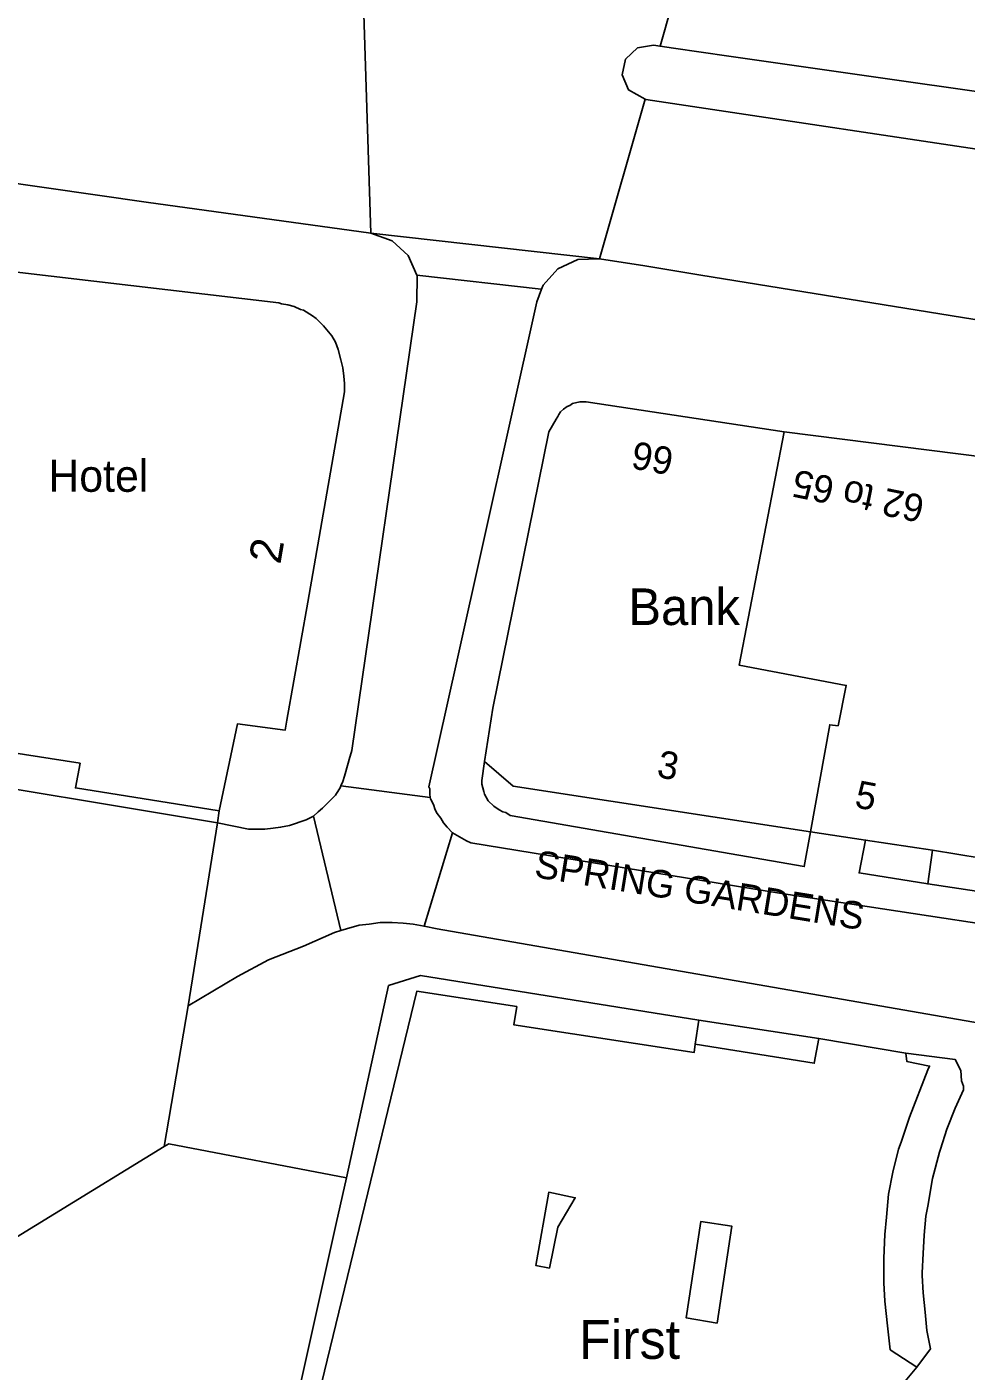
# Model space of a CAD drawing. Extents: x 529240 to 530363, y 179600 to 180767.
# Drawn here: x 529918.6 to 529969.9, y 180321.7 to 180395.2 of the extents above; entities that cross this region are included whole.
import ezdxf

# ---------------------------------------------------------------- set-up
doc = ezdxf.new("R2010")
doc.units = 0
for name, color, linetype in [('Building', 7, 'Continuous'), ('General surface', 7, 'Continuous'), ('Road Or Track', 7, 'Continuous'), ('Roadside', 7, 'Continuous'), ('Unclassified', 7, 'Continuous')]:
    doc.layers.add(name, color=color, linetype=linetype)

msp = doc.modelspace()

# ---------------------------------------------------------------- linework, layer by layer
at = {"layer": 'Building'}
for points in [[(529917.7, 180355.55), (529921.55, 180354.95), (529921.3, 180353.6), (529929.15, 180352.35), (529930.15, 180357.1), (529932.75, 180356.75), (529932.85, 180357.3), (529934, 180363.75), (529936, 180375.25), (529936, 180375.7), (529935.95, 180376.1), (529935.9, 180376.55), (529935.8, 180377), (529935.65, 180377.55), (529935.5, 180377.95), (529935.3, 180378.3), (529934.85, 180378.85), (529934.45, 180379.25), (529934.25, 180379.4), (529933.75, 180379.7), (529933.6, 180379.75), (529933.25, 180379.9), (529932.9, 180380), (529932.55, 180380.05), (529932.4, 180380.1), (529909.85, 180382.75)], [(529929.15, 180352.35), (529930.15, 180357.1), (529932.75, 180356.75), (529932.85, 180357.3), (529934, 180363.75), (529936, 180375.25), (529936, 180375.7), (529935.95, 180376.1), (529935.9, 180376.55), (529935.8, 180377), (529935.65, 180377.55), (529935.5, 180377.95), (529935.3, 180378.3), (529934.85, 180378.85), (529934.45, 180379.25), (529934.25, 180379.4), (529933.75, 180379.7), (529933.6, 180379.75), (529933.25, 180379.9), (529932.9, 180380), (529932.55, 180380.05), (529932.4, 180380.1), (529909.85, 180382.75)], [(529960, 180373.05), (529949.2, 180374.7), (529948.85, 180374.7), (529948.45, 180374.6), (529948.3, 180374.5), (529948.15, 180374.45), (529947.95, 180374.3), (529947.8, 180374.15), (529947.7, 180374), (529947.65, 180373.9), (529947.55, 180373.75), (529947.15, 180373.05), (529944.1, 180357.95), (529943.65, 180355.05)], [(529960, 180373.05), (529957.55, 180360.3), (529963.4, 180359.2), (529962.95, 180357), (529962.5, 180357.05), (529961.45, 180351.2)], [(529975.85, 180371.05), (529960, 180373.05)], [(529929.15, 180352.35), (529921.3, 180353.6), (529921.55, 180354.95), (529917.7, 180355.55), (529917.55, 180354.4), (529912.3, 180355.15)], [(529943.65, 180355.05), (529945.2, 180353.7), (529961.45, 180351.2)], [(529929.05, 180351.7), (529929.15, 180352.35)], [(529927.45, 180341.7), (529929.05, 180351.7)], [(529961.45, 180351.2), (529964.45, 180350.75)], [(529964.45, 180350.75), (529968.1, 180350.2)], [(529968.1, 180350.2), (529972.1, 180349.55)], [(529966.25, 180320.75), (529967.25, 180321.95), (529965.8, 180322.9), (529965.65, 180324.2), (529965.5, 180325.55), (529965.45, 180326.55), (529965.45, 180327.9), (529965.5, 180329.2), (529965.6, 180330.15), (529965.7, 180331.4), (529965.95, 180332.6), (529966.25, 180333.85), (529966.4, 180334.25), (529966.85, 180335.6), (529967.85, 180338.2), (529967.95, 180338.4), (529966.7, 180338.65), (529966.65, 180339.1), (529961.9, 180339.9), (529961.65, 180338.55), (529955.15, 180339.6), (529955.1, 180339.15), (529945.25, 180340.65), (529945.4, 180341.65), (529939.95, 180342.5), (529933.8, 180317.15)], [(529955.15, 180339.6), (529955.1, 180339.15), (529945.25, 180340.65), (529945.4, 180341.65), (529939.95, 180342.5), (529933.8, 180317.15)], [(529926.15, 180334), (529927.45, 180341.7)], [(529961.9, 180339.9), (529961.65, 180338.55), (529955.15, 180339.6)], [(529966.65, 180339.1), (529961.9, 180339.9)], [(529967.25, 180321.95), (529965.8, 180322.9), (529965.65, 180324.2), (529965.5, 180325.55), (529965.45, 180326.55), (529965.45, 180327.9), (529965.5, 180329.2), (529965.6, 180330.15), (529965.7, 180331.4), (529965.95, 180332.6), (529966.25, 180333.85), (529966.4, 180334.25), (529966.85, 180335.6), (529967.85, 180338.2), (529967.95, 180338.4), (529966.7, 180338.65), (529966.65, 180339.1)], [(529914.15, 180326.65), (529926.15, 180334)], [(529926.15, 180334), (529926.4, 180334.15)], [(529947.2, 180327.35), (529947.65, 180329.6), (529948.6, 180331.2), (529947.15, 180331.5), (529946.45, 180327.5), (529947.2, 180327.35)], [(529956.35, 180324.35), (529954.65, 180324.65), (529955.45, 180329.9), (529957.15, 180329.65), (529956.35, 180324.35)], [(529966.25, 180320.75), (529967.25, 180321.95)]]:
    msp.add_lwpolyline(points, dxfattribs=at)
for points in [[(529961.45, 180351.2), (529962.5, 180357.05), (529962.95, 180357), (529963.4, 180359.2), (529957.55, 180360.3), (529960, 180373.05), (529949.2, 180374.7), (529948.85, 180374.7), (529948.45, 180374.6), (529948.3, 180374.5), (529948.15, 180374.45), (529947.95, 180374.3), (529947.8, 180374.15), (529947.7, 180374), (529947.65, 180373.9), (529947.55, 180373.75), (529947.15, 180373.05), (529944.1, 180357.95), (529943.65, 180355.05), (529945.2, 180353.7)], [(529968.1, 180350.2), (529972.1, 180349.55), (529973.45, 180355.3), (529973.95, 180355.2), (529974.65, 180358.1), (529972.65, 180357.5), (529971.65, 180357.7), (529972.75, 180362), (529973.7, 180365.65), (529974.4, 180365.5), (529975.85, 180371.05), (529960, 180373.05), (529957.55, 180360.3), (529963.4, 180359.2), (529962.95, 180357), (529962.5, 180357.05), (529961.45, 180351.2), (529964.45, 180350.75)], [(529912.3, 180355.15), (529912.2, 180354.5), (529911.5, 180349.9), (529911.05, 180347), (529908.45, 180345.5), (529904.9, 180343.5), (529904.15, 180343.05), (529914.15, 180326.65), (529926.15, 180334), (529927.45, 180341.7), (529929.05, 180351.7), (529929.15, 180352.35), (529921.3, 180353.6), (529921.55, 180354.95), (529917.7, 180355.55), (529917.55, 180354.4)], [(529947.2, 180327.35), (529947.65, 180329.6), (529948.6, 180331.2), (529947.15, 180331.5), (529946.45, 180327.5)], [(529956.35, 180324.35), (529957.15, 180329.65), (529955.45, 180329.9), (529954.65, 180324.65)]]:
    msp.add_lwpolyline(points, close=True, dxfattribs=at)
at = {"layer": 'General surface'}
for points in [[(529943.65, 180355.05), (529943.5, 180354), (529943.5, 180353.8), (529943.6, 180353.4), (529943.65, 180353.25), (529943.85, 180352.9), (529944.15, 180352.6), (529944.45, 180352.4), (529944.65, 180352.3), (529944.8, 180352.25), (529945.05, 180352.1), (529961.1, 180349.3), (529961.45, 180351.2), (529945.2, 180353.7)], [(529967.85, 180348.35), (529968.1, 180350.2), (529964.45, 180350.75), (529964.1, 180348.95)], [(529971.85, 180347.75), (529972.1, 180349.55), (529968.1, 180350.2), (529967.85, 180348.35)], [(529961.9, 180339.9), (529955.35, 180340.9), (529955.15, 180339.6), (529961.65, 180338.55)], [(529967.25, 180321.95), (529968, 180322.95), (529967.8, 180323.95), (529967.7, 180324.95), (529967.6, 180326), (529967.55, 180326.95), (529967.55, 180327.1), (529967.6, 180328.15), (529967.65, 180329.15), (529967.75, 180330.2), (529967.85, 180330.75), (529968.1, 180332.25), (529968.5, 180333.7), (529968.55, 180333.85), (529968.9, 180334.95), (529969.35, 180336.1), (529969.8, 180337.1), (529969.8, 180337.3), (529969.7, 180337.6), (529969.65, 180338.15), (529969.35, 180338.75), (529966.65, 180339.1), (529966.7, 180338.65), (529967.95, 180338.4), (529967.85, 180338.2), (529966.85, 180335.6), (529966.4, 180334.25), (529966.25, 180333.85), (529965.95, 180332.6), (529965.7, 180331.4), (529965.6, 180330.15), (529965.5, 180329.2), (529965.45, 180327.9), (529965.45, 180326.55), (529965.5, 180325.55), (529965.65, 180324.2), (529965.8, 180322.9)], [(529947.2, 180327.35), (529947.65, 180329.6), (529948.6, 180331.2), (529947.15, 180331.5), (529946.45, 180327.5)], [(529956.35, 180324.35), (529957.15, 180329.65), (529955.45, 180329.9), (529954.65, 180324.65)]]:
    msp.add_lwpolyline(points, close=True, dxfattribs=at)
for points in [[(529933.8, 180317.15), (529939.95, 180342.5), (529945.4, 180341.65), (529945.25, 180340.65), (529955.1, 180339.15), (529955.15, 180339.6), (529955.35, 180340.9), (529940.15, 180343.35), (529938.4, 180342.8), (529936.1, 180332.3), (529935.54, 180329.79), (529932.3, 180315.2)], [(529932.3, 180315.2), (529935.54, 180329.79), (529936.1, 180332.3), (529926.4, 180334.15), (529926.15, 180334), (529914.15, 180326.65)]]:
    msp.add_lwpolyline(points, dxfattribs=at)
at = {"layer": 'Road Or Track'}
for points in [[(529936.88, 180401.04), (529915.75, 180404.08), (529868.32, 180410.91), (529862.53, 180412.05), (529857.93, 180413.41), (529853.46, 180415.16), (529852.45, 180415.73), (529846.38, 180413.91), (529846.36, 180413.54), (529845.88, 180413.25), (529847.53, 180409.14), (529847.95, 180408.85), (529848.85, 180406.97), (529848.84, 180406.5), (529848.33, 180406.26), (529847.75, 180400.26), (529865.5, 180397.61), (529865.59, 180397.6), (529878.05, 180392.38), (529925.17, 180385.6), (529937.44, 180383.91)], [(529937.44, 180383.91), (529949.92, 180382.52), (529952.41, 180391.23), (529951.5, 180391.74), (529951.16, 180392.56), (529951.35, 180393.43), (529952, 180394.04), (529952.87, 180394.18), (529953.23, 180394.13), (529954.48, 180398.5), (529936.88, 180401.04)], [(530005.28, 180368.4), (530006.1, 180378.46), (530001.57, 180380.79), (530000, 180381.45), (529996.86, 180382.76), (529992.02, 180384.36), (529987.07, 180385.57), (529972.72, 180388.17), (529953.54, 180391.05), (529952.45, 180391.21), (529952.41, 180391.23), (529949.92, 180382.52), (529952.4, 180382.12), (529955.46, 180381.62), (529986.51, 180376.59), (529989.29, 180377.65), (529989.92, 180377.68), (529991.21, 180377.23), (529996.68, 180375.3), (529996.77, 180375.26), (529998.99, 180374.16), (530000, 180373.48), (530001.47, 180372.48), (530003.69, 180370.47)], [(529949.92, 180382.52), (529937.44, 180383.91), (529938.6, 180383.5), (529939.47, 180382.69), (529939.95, 180381.62), (529946.73, 180380.86), (529946.76, 180380.85), (529946.85, 180381.08), (529947.65, 180381.97), (529948.73, 180382.48)], [(529935.8, 180353.71), (529940.68, 180353.08), (529940.65, 180353.25), (529940.65, 180353.55), (529940.6, 180353.65), (529942.15, 180360.6), (529946.5, 180380.16), (529946.76, 180380.85), (529946.73, 180380.86), (529939.95, 180381.62), (529939.96, 180381.6), (529939.95, 180380.17), (529936.4, 180355.65), (529936.25, 180355.15), (529936.2, 180354.95), (529936, 180354.25), (529935.9, 180353.95)], [(529934.3, 180352.05), (529935.8, 180345.81), (529936.1, 180345.9), (529936.8, 180346.1), (529937.35, 180346.15), (529937.95, 180346.25), (529938.6, 180346.25), (529939.2, 180346.2), (529939.75, 180346.15), (529940.34, 180346.04), (529941.9, 180351.15), (529941.6, 180351.45), (529941.4, 180351.7), (529941.25, 180351.95), (529941.05, 180352.2), (529940.95, 180352.4), (529940.85, 180352.7), (529940.7, 180353), (529940.68, 180353.08), (529935.8, 180353.71), (529935.75, 180353.6), (529935.55, 180353.3), (529935.5, 180353.2), (529934.8, 180352.5), (529934.55, 180352.3)], [(529927.45, 180341.7), (529930.15, 180343.3), (529931.85, 180344.2), (529933.75, 180344.95), (529935.45, 180345.7), (529935.8, 180345.81), (529934.3, 180352.05), (529933.9, 180351.85), (529933, 180351.55), (529932.5, 180351.45), (529932.1, 180351.4), (529931.65, 180351.35), (529930.75, 180351.35), (529929.05, 180351.7)], [(529940.34, 180346.04), (529941.05, 180345.9), (529973.18, 180340.31), (529974.53, 180340.07), (529982.61, 180338.66), (529982.88, 180338.55), (529982.9, 180338.56), (529984.57, 180339.7), (529986.98, 180340.9), (529989.55, 180341.72), (529985.6, 180343.91), (529959.75, 180347.85), (529942.9, 180350.6), (529942.65, 180350.7), (529941.9, 180351.15)]]:
    msp.add_lwpolyline(points, close=True, dxfattribs=at)
for points in [[(529954.48, 180398.5), (529953.23, 180394.13), (529953.97, 180394.02), (529956.99, 180393.59), (529979.3, 180390.4), (529985.56, 180389.7), (529994.89, 180389.4), (529999.38, 180389.68), (530000, 180389.77), (530000.2, 180389.8), (530003.82, 180390.38), (530011.94, 180392.6), (530010.83, 180400.08)], [(529953.23, 180394.13), (529952.87, 180394.18), (529952, 180394.04), (529951.35, 180393.43), (529951.16, 180392.56), (529951.5, 180391.74), (529952.41, 180391.23)], [(530011.94, 180392.6), (530003.82, 180390.38), (530000.2, 180389.8), (530000, 180389.77), (529999.38, 180389.68), (529994.89, 180389.4), (529985.56, 180389.7), (529979.3, 180390.4), (529956.99, 180393.59), (529953.97, 180394.02), (529953.23, 180394.13)], [(529937.44, 180383.91), (529925.17, 180385.6), (529878.05, 180392.38)], [(529952.41, 180391.23), (529952.45, 180391.21), (529953.54, 180391.05), (529972.72, 180388.17), (529987.07, 180385.57), (529992.02, 180384.36), (529996.86, 180382.76), (530000, 180381.45), (530001.57, 180380.79), (530006.1, 180378.46)], [(529939.95, 180381.62), (529939.47, 180382.69), (529938.6, 180383.5), (529937.44, 180383.91)], [(529949.92, 180382.52), (529937.44, 180383.91)], [(529946.76, 180380.85), (529946.85, 180381.08), (529947.65, 180381.97), (529948.73, 180382.48), (529949.92, 180382.52)], [(529949.92, 180382.52), (529952.4, 180382.12), (529955.46, 180381.62), (529986.51, 180376.59), (529989.29, 180377.65), (529989.92, 180377.68), (529991.21, 180377.23), (529996.68, 180375.3), (529996.77, 180375.26), (529998.99, 180374.16), (530000, 180373.48), (530001.47, 180372.48), (530003.69, 180370.47), (530005.28, 180368.4)], [(529939.95, 180380.17), (529939.96, 180381.6), (529939.95, 180381.62)], [(529946.76, 180380.85), (529946.73, 180380.86), (529939.95, 180381.62)], [(529940.68, 180353.08), (529940.65, 180353.25), (529940.65, 180353.55), (529940.6, 180353.65), (529942.15, 180360.6), (529946.5, 180380.16), (529946.76, 180380.85)], [(529939.95, 180380.17), (529936.4, 180355.65)], [(529935.8, 180353.71), (529935.9, 180353.95), (529936, 180354.25), (529936.2, 180354.95), (529936.25, 180355.15), (529936.4, 180355.65)], [(529934.3, 180352.05), (529934.55, 180352.3), (529934.8, 180352.5), (529935.5, 180353.2), (529935.55, 180353.3), (529935.75, 180353.6), (529935.8, 180353.71)], [(529941.9, 180351.15), (529941.6, 180351.45), (529941.4, 180351.7), (529941.25, 180351.95), (529941.05, 180352.2), (529940.95, 180352.4), (529940.85, 180352.7), (529940.7, 180353), (529940.68, 180353.08)], [(529929.05, 180351.7), (529930.75, 180351.35), (529931.65, 180351.35), (529932.1, 180351.4), (529932.5, 180351.45), (529933, 180351.55), (529933.9, 180351.85), (529934.3, 180352.05)], [(529989.55, 180341.72), (529985.6, 180343.91), (529959.75, 180347.85), (529942.9, 180350.6), (529942.65, 180350.7), (529941.9, 180351.15)], [(529940.34, 180346.04), (529939.75, 180346.15), (529939.2, 180346.2), (529938.6, 180346.25), (529937.95, 180346.25), (529937.35, 180346.15), (529936.8, 180346.1), (529936.1, 180345.9), (529935.8, 180345.81)], [(529935.8, 180345.81), (529935.45, 180345.7), (529933.75, 180344.95), (529931.85, 180344.2), (529930.15, 180343.3), (529927.45, 180341.7)], [(529973.18, 180340.31), (529941.05, 180345.9), (529940.34, 180346.04)]]:
    msp.add_lwpolyline(points, dxfattribs=at)
at = {"layer": 'Roadside'}
for points in [[(529979.3, 180390.4), (529956.99, 180393.59), (529953.97, 180394.02), (529953.23, 180394.13), (529952.87, 180394.18), (529952, 180394.04), (529951.35, 180393.43), (529951.16, 180392.56), (529951.5, 180391.74), (529952.41, 180391.23), (529952.45, 180391.21), (529953.54, 180391.05), (529972.72, 180388.17)], [(529909.85, 180382.75), (529932.4, 180380.1), (529932.55, 180380.05), (529932.9, 180380), (529933.25, 180379.9), (529933.6, 180379.75), (529933.75, 180379.7), (529934.25, 180379.4), (529934.45, 180379.25), (529934.85, 180378.85), (529935.3, 180378.3), (529935.5, 180377.95), (529935.65, 180377.55), (529935.8, 180377), (529935.9, 180376.55), (529935.95, 180376.1), (529936, 180375.7), (529936, 180375.25), (529934, 180363.75), (529932.85, 180357.3), (529932.75, 180356.75), (529930.15, 180357.1), (529929.15, 180352.35), (529929.05, 180351.7), (529930.75, 180351.35), (529931.65, 180351.35), (529932.1, 180351.4), (529932.5, 180351.45), (529933, 180351.55), (529933.9, 180351.85), (529934.3, 180352.05), (529934.55, 180352.3), (529934.8, 180352.5), (529935.5, 180353.2), (529935.55, 180353.3), (529935.75, 180353.6), (529935.8, 180353.71), (529935.9, 180353.95), (529936, 180354.25), (529936.2, 180354.95), (529936.25, 180355.15), (529936.4, 180355.65), (529939.95, 180380.17), (529939.96, 180381.6), (529939.95, 180381.62), (529939.47, 180382.69), (529938.6, 180383.5), (529937.44, 180383.91), (529925.17, 180385.6), (529878.05, 180392.38)], [(529986.51, 180376.59), (529955.46, 180381.62), (529952.4, 180382.12), (529949.92, 180382.52), (529948.73, 180382.48), (529947.65, 180381.97), (529946.85, 180381.08), (529946.76, 180380.85), (529946.5, 180380.16), (529942.15, 180360.6), (529940.6, 180353.65), (529940.65, 180353.55), (529940.65, 180353.25), (529940.68, 180353.08), (529940.7, 180353), (529940.85, 180352.7), (529940.95, 180352.4), (529941.05, 180352.2), (529941.25, 180351.95), (529941.4, 180351.7), (529941.6, 180351.45), (529941.9, 180351.15), (529942.65, 180350.7), (529942.9, 180350.6), (529959.75, 180347.85), (529985.6, 180343.91)], [(529975.85, 180371.05), (529960, 180373.05), (529949.2, 180374.7), (529948.85, 180374.7), (529948.45, 180374.6), (529948.3, 180374.5), (529948.15, 180374.45), (529947.95, 180374.3), (529947.8, 180374.15), (529947.7, 180374), (529947.65, 180373.9), (529947.55, 180373.75), (529947.15, 180373.05), (529944.1, 180357.95), (529943.65, 180355.05), (529943.5, 180354), (529943.5, 180353.8), (529943.6, 180353.4), (529943.65, 180353.25), (529943.85, 180352.9), (529944.15, 180352.6), (529944.45, 180352.4), (529944.65, 180352.3), (529944.8, 180352.25), (529945.05, 180352.1), (529961.1, 180349.3), (529961.45, 180351.2), (529964.45, 180350.75), (529964.1, 180348.95), (529967.85, 180348.35), (529971.85, 180347.75)], [(529973.18, 180340.31), (529941.05, 180345.9), (529940.34, 180346.04), (529939.75, 180346.15), (529939.2, 180346.2), (529938.6, 180346.25), (529937.95, 180346.25), (529937.35, 180346.15), (529936.8, 180346.1), (529936.1, 180345.9), (529935.8, 180345.81), (529935.45, 180345.7), (529933.75, 180344.95), (529931.85, 180344.2), (529930.15, 180343.3), (529927.45, 180341.7), (529926.15, 180334), (529926.4, 180334.15), (529936.1, 180332.3), (529938.4, 180342.8), (529940.15, 180343.35), (529955.35, 180340.9), (529961.9, 180339.9), (529966.65, 180339.1), (529969.35, 180338.75), (529969.65, 180338.15), (529969.7, 180337.6), (529969.8, 180337.3), (529969.8, 180337.1), (529969.35, 180336.1), (529968.9, 180334.95), (529968.55, 180333.85), (529968.5, 180333.7), (529968.1, 180332.25), (529967.85, 180330.75), (529967.75, 180330.2), (529967.65, 180329.15), (529967.6, 180328.15), (529967.55, 180327.1), (529967.55, 180326.95), (529967.6, 180326), (529967.7, 180324.95), (529967.8, 180323.95), (529968, 180322.95), (529967.25, 180321.95), (529966.25, 180320.75)]]:
    msp.add_lwpolyline(points, dxfattribs=at)
at = {"layer": 'Unclassified'}
for points in [[(529937.44, 180383.91), (529936.88, 180401.04)], [(529954.48, 180398.5), (529953.23, 180394.13)], [(529952.41, 180391.23), (529949.92, 180382.52)], [(529943.65, 180355.05), (529943.5, 180354), (529943.5, 180353.8), (529943.6, 180353.4), (529943.65, 180353.25), (529943.85, 180352.9), (529944.15, 180352.6), (529944.45, 180352.4), (529944.65, 180352.3), (529944.8, 180352.25), (529945.05, 180352.1), (529961.1, 180349.3), (529961.45, 180351.2)], [(529912.2, 180354.5), (529929.05, 180351.7)], [(529940.68, 180353.08), (529935.8, 180353.71)], [(529934.3, 180352.05), (529935.8, 180345.81)], [(529941.9, 180351.15), (529940.34, 180346.04)], [(529964.45, 180350.75), (529964.1, 180348.95), (529967.85, 180348.35)], [(529967.85, 180348.35), (529968.1, 180350.2)], [(529967.85, 180348.35), (529971.85, 180347.75)], [(529940.15, 180343.35), (529938.4, 180342.8), (529936.1, 180332.3)], [(529955.35, 180340.9), (529940.15, 180343.35)], [(529955.35, 180340.9), (529955.15, 180339.6)], [(529961.9, 180339.9), (529955.35, 180340.9)], [(529967.25, 180321.95), (529968, 180322.95), (529967.8, 180323.95), (529967.7, 180324.95), (529967.6, 180326), (529967.55, 180326.95), (529967.55, 180327.1), (529967.6, 180328.15), (529967.65, 180329.15), (529967.75, 180330.2), (529967.85, 180330.75), (529968.1, 180332.25), (529968.5, 180333.7), (529968.55, 180333.85), (529968.9, 180334.95), (529969.35, 180336.1), (529969.8, 180337.1), (529969.8, 180337.3), (529969.7, 180337.6), (529969.65, 180338.15), (529969.35, 180338.75), (529966.65, 180339.1)], [(529926.4, 180334.15), (529936.1, 180332.3)], [(529936.1, 180332.3), (529935.54, 180329.79), (529932.3, 180315.2), (529935.8, 180310.2)]]:
    msp.add_lwpolyline(points, dxfattribs=at)

# ---------------------------------------------------------------- texts
at = {"layer": 'Road Or Track'}
msp.add_text('SPRING GARDENS', height=1.5, rotation=350.8, dxfattribs=at).set_placement((529946.31, 180348.73))
at = {"layer": 'Unclassified'}
for s, height, rotation, p in [('66', 1.5, 169.6, (529954.05, 180372.15)), ('62 to 65', 1.5, 168.4, (529967.75, 180369.55)), ('2', 1.75, 80.4, (529932.49, 180365.78)), ('3', 1.5, 349.9, (529953, 180354.2)), ('5', 1.5, 349.3, (529963.8, 180352.55))]:
    msp.add_text(s, height=height, rotation=rotation, dxfattribs=at).set_placement(p)
for s, height, p in [('Hotel', 1.75, (529919.82, 180369.78)), ('Bank', 2, (529951.5, 180362.5)), ('First', 2.125, (529948.8, 180322.4))]:
    msp.add_text(s, height=height, dxfattribs=at).set_placement(p)

doc.saveas('drawing.dxf')
